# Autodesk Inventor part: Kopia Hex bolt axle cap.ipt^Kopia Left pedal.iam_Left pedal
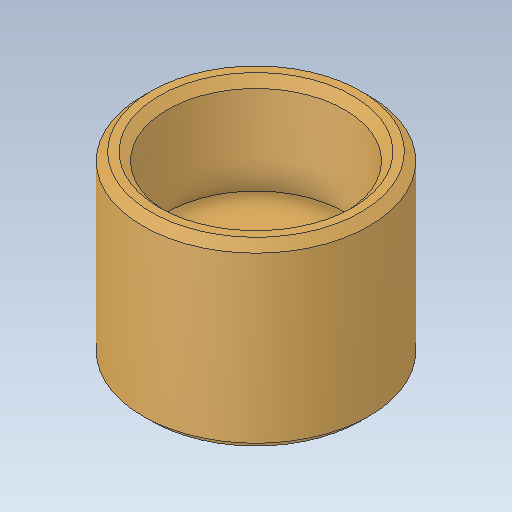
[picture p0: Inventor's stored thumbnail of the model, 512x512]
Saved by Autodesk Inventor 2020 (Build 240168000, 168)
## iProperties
Created: 2017-10
Part Number: Kopia Hex bolt axle cap.ipt^Kopia Left pedal.iam_Left pedal
Material: solidworks materials|6061-T6 (SS)|164
Document SubType Name: Modeling
Designer: Tomasz
Density: 2.7 g/cm^3
Appearance: 221,232,255
Sending System: SolidWorks 2017
Last Author: Tomasz
Last Saved: 2017-11-19
Author: Tomasz
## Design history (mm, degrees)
feature "Hex bolt axle cap.ipt"
node "Bryła1"
